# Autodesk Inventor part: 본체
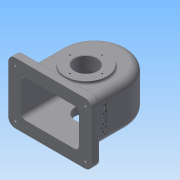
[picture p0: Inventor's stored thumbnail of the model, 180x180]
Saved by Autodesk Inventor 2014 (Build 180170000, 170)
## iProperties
Created: 2016-10
Part Number: 본체
Material: 일반
Document SubType Name: Modeling
Designer: net
Density: 1 g/cm^3
Appearance: 기본값
Author: net
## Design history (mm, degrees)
sketch "스케치1"
  geometry: L1 (-63, 55)-(63, 55); L2 (75, 43)-(75, -43); L3 (63, -55)-(-63, -55); L4 (-75, -43)-(-75, 43); L5 (-75, 55)-(75, -55); L6 (75, 55)-(-75, -55); A1 r 12 centre (63, -43) between (63, -55) and (75, -43); A2 r 12 centre (-63, -43) between (-75, -43) and (-63, -55); A3 r 12 centre (-63, 43) between (-63, 55) and (-75, 43); A4 r 12 centre (63, 43) between (75, 43) and (63, 55); 1 further point
  constraints: 12 end point, 8 point on circle, 8 point on line, 8 tangent, 4 centre point, 3 equal radius, 2 midpoint, 2 parallel, 1 horizontal, 1 perpendicular
  dimensions: "d0" = 150 distance of L5.end L6.end; "d1" = 110 distance of L6.start L5.end; "d2" = 12 radius of A1
extrude "돌출1" new body sketch "스케치1" distance "d3" = 15; taper "d4" = 0 deg
fillet "모깎기1" dims "d5" = 3
sketch "스케치2"
  geometry: L1 (-58, 0)-(58, 0); L2 (58, 0)-(58, 80); L3 (58, 80)-(-58, 80); L4 (-58, 80)-(-58, 0); 2 further points
  constraints: 8 end point, 2 coincident, 2 parallel, 1 horizontal, 1 midpoint, 1 perpendicular
  dimensions: "d6" = 116 distance of L3.end L2.end; "d7" = 80 distance of L2.end L1.end
extrude "돌출2" join sketch "스케치2" stored distance "d8" = 77; taper "d9" = 0 deg
sketch "스케치3"
  geometry: L1 (-58, 80)-(58, 80) reference; 2 further points
  constraints: 1 horizontal alignment, 1 midpoint, 2 other
extrude "돌출3" join sketch "스케치3" stored distance "d10" = 77; taper "d11" = 0 deg
sketch "스케치4"
  geometry: L1 (-58, 15)-(-58, 80) reference; L2 (58, 80)-(58, 15) reference; L3 (-63, 0)-(63, 0) reference; L4 (-52, 0)-(-52, 80); L5 (52, 80)-(52, 0); L6 (52, 0)-(-52, 0); A1 r 58 centre (0, 80) between (58, 80) and (-58, 80) reference; A2 r 52 centre (0, 80) between (52, 80) and (-52, 80); 1 further point
  constraints: 6 end point, 2 parallel, 2 point on circle, 2 point on line, 2 tangent, 1 centre point, 1 collinear
  dimensions: "d12" = 6 radial gap between concentric circles of A2 A1
extrude "돌출4" cut sketch "스케치4" stored distance "d13" = 67; taper "d14" = 0 deg
sketch "스케치5"
  geometry: L1 (63, 0)-(-63, 0) reference; C1 r 31 at (0, 65); 2 further points
  constraints: 1 centre point, 1 midpoint, 1 vertical alignment
  dimensions: "d15" = 62 diameter of C1; "d16" = 65 distance from line of L1 C1.centre
extrude "돌출5" join sketch "스케치5" distance "d17" = 10; taper "d18" = 0 deg
sketch "스케치6"
  geometry: C1 r 31 at (0, 0) reference; C2 r 20 at (0, 0); 1 further point
  constraints: 1 centre point, 1 coincident
  dimensions: "d19" = 40 diameter of C2
extrude "돌출6" cut sketch "스케치6" distance "d20" = 15; taper "d21" = 0 deg
sketch "스케치7"
  geometry: L1 (63, 0)-(-63, 0) reference; C1 r 37.5 at (0, 65); 2 further points
  constraints: 1 centre point, 1 midpoint, 1 vertical alignment
  dimensions: "d22" = 75 diameter of C1; "d23" = 65 distance from line of L1 C1.centre
extrude "돌출7" join sketch "스케치7" distance "d24" = 5; taper "d25" = 0 deg
sketch "스케치8"
  geometry: C1 r 37.5 at (0, 0) reference; C2 r 20 at (0, 0); 1 further point
  constraints: 1 centre point, 1 coincident
  dimensions: "d26" = 40 diameter of C2
extrude "돌출8" cut sketch "스케치8" distance "d27" = 24; taper "d28" = 0 deg
sketch "스케치9"
  geometry: C1 r 20 at (0, 65) reference; C2 r 28 at (0, 65); 1 further point
  constraints: 1 centre point, 1 coincident
  dimensions: "d29" = 56 diameter of C2
extrude "돌출9" join sketch "스케치9" distance "d30" = 14; taper "d31" = 0 deg
feature "면 기울기1" dims angle "d32" = 40 deg
sketch "스케치11"
  geometry: A1 r 9 centre (63, 43) between (72, 43) and (63, 52) reference; A2 r 9 centre (-63, 43) between (-63, 52) and (-72, 43) reference; A3 r 9 centre (-63, -43) between (-72, -43) and (-63, -52) reference; A4 r 9 centre (63, -43) between (63, -52) and (72, -43) reference; 5 further points
  constraints: 4 coincident
hole "구멍1" sketch "스케치11" at (-63, 43), (63, 43), (63, -43), (-63, -43) diameter "d33" = 5; stored, may be unused: countersink angle "d37" = 90 deg, drill point angle "d39" = 0 deg; dims "d34" = 6, "d35" = 12, "d36" = 5, "d38" = 20
fillet "모깎기2" dims "d40" = 13, "d41" = 8
node "작업 평면1"
sketch "스케치12"
  geometry: C1 r 6 at (0, 0); 1 further point
  constraints: 1 centre point, 1 coincident
  dimensions: "d43" = 12 diameter of C1
extrude "돌출10" join sketch "스케치12" stored distance "d44" = 14; taper "d45" = 0 deg
feature "면 기울기2" dims angle "d46" = 10 deg
sketch "스케치14"
  geometry: C1 r 6 at (0, 0) reference; 1 further point
  constraints: 1 coincident
hole "구멍2" sketch "스케치14" at (0, 0) diameter "d47" = 4.459; stored, may be unused: countersink angle "d51" = 90 deg, drill point angle "d53" = 118 deg; dims "d48" = 30, "d49" = 12, "d50" = 5, "d52" = 30
sketch "스케치15"
  geometry: C1 r 20 at (0, 0) reference; 5 further points
  constraints: 1 horizontal alignment, 5 other
  dimensions: "d54" = 29 distance of point (29, 0) C1.centre; "d57" = 360 deg dimension on C1.centre point (29, 0) (derived)
hole "구멍3" sketch "스케치15" at (29, 0), (0, 29), (-29, 0), (0, -29) diameter "d59" = 2.459; stored, may be unused: countersink angle "d63" = 90 deg, drill point angle "d65" = 118 deg; dims "d60" = 6, "d61" = 4, "d62" = 2, "d64" = 8
sketch "스케치16"
  geometry: C1 r 20 at (0, 0) reference; 5 further points
  constraints: 1 horizontal alignment, 5 other
  dimensions: "d66" = 26 distance of point (26, 0) C1.centre; "d69" = 360 deg dimension on C1.centre point (26, 0) (derived)
hole "구멍4" sketch "스케치16" at (26, 0), (0, 26), (-26, 0), (0, -26) diameter "d71" = 2.459; stored, may be unused: countersink angle "d75" = 90 deg, drill point angle "d77" = 118 deg; dims "d72" = 6, "d73" = 4, "d74" = 2, "d76" = 8
chamfer "모따기1" distance "d78" = 1; stored, may be unused: second distance "d79" = 2, angle "d80" = 45 deg
node "작업 평면2"
sketch "스케치17"
  geometry: L1 (17.5, -15)-(-68.5, -15) reference; 3 further points
  constraints: 1 midpoint, 1 vertical alignment, 1 other
  dimensions: "d82" = 40 distance from line of L1 point (-25.5, 25)
feature "엠보싱1" sketch "스케치17" dims "d0" = 150, "d1" = 110, "d2" = 12, "d83" = 0.5, "d84" = 0
fillet "모깎기3" dims "d85" = 3
node "솔리드1"
other parameters: "d42" = 144, "d81" = 5
